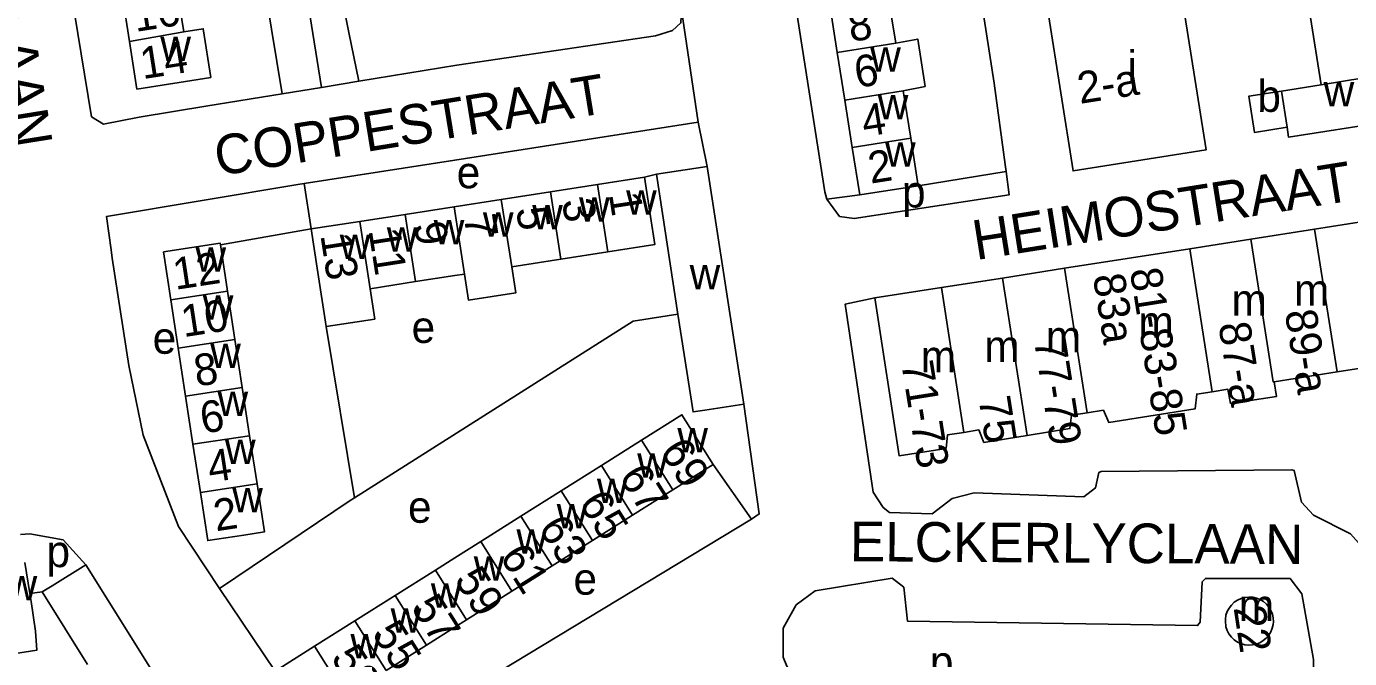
# Model space of a CAD drawing. Extents: x 159675 to 162108, y 386471 to 388472.
# Drawn here: x 160445.9 to 160612.9, y 387264.8 to 387344.6 of the extents above; entities that cross this region are included whole.
import ezdxf

# ---------------------------------------------------------------- set-up
doc = ezdxf.new("R2010")
doc.units = 0
for name, color, linetype in [('BLT_Basislijn', 7, 'Continuous'), ('BLT_Bebouwing', 7, 'Continuous'), ('BLT_Centroide', 7, 'Continuous'), ('BLT_Huisnummer', 7, 'Continuous'), ('BLT_Huisnummer_ tussenligend', 7, 'Continuous'), ('BLT_Huisnummer_reeks', 7, 'Continuous'), ('BLT_Onderverdeling_panden', 7, 'Continuous'), ('BLT_Straatnaam', 7, 'Continuous'), ('BLT_Vlakafsluiter', 7, 'Continuous')]:
    doc.layers.add(name, color=color, linetype=linetype)

msp = doc.modelspace()

# ---------------------------------------------------------------- linework, layer by layer
at = {"layer": 'BLT_Basislijn'}
for p, q in [((160463.22, 387427.52), (160478.22, 387336.11)), ((160486.63, 387343.84), (160485.9, 387347.45)), ((160487.88, 387337.71), (160486.63, 387343.84)), ((160487.88, 387337.71), (160483.16, 387336.93)), ((160478.22, 387336.11), (160483.16, 387336.93)), ((160460.17, 387333.18), (160468.84, 387334.58)), ((160525.44, 387325.97), (160523.93, 387325.58)), ((160569.58, 387326.3), (160558.48, 387324.51)), ((160481.87, 387319.06), (160480.99, 387324.78)), ((160546.94, 387322.82), (160551.1, 387323.35)), ((160470.42, 387317.06), (160481.87, 387319.06)), ((160522.52, 387307.43), (160487.33, 387285.14)), ((160522.52, 387307.43), (160528.16, 387308.3)), ((160483.78, 387306.73), (160487.33, 387285.14)), ((160537.44, 387282.44), (160532.61, 387289.34)), ((160446.36, 387273.07), (160447.91, 387273.25)), ((160477.32, 387263.27), (160470.32, 387273.7))]:
    msp.add_line(p, q, dxfattribs=at)
for points in [[(160549.16, 387459.3), (160568.08, 387337.47), (160569.46, 387327.2), (160569.58, 387326.3)], [(160526.05, 387455.64), (160546.72, 387323.73), (160546.94, 387322.82)], [(160483.16, 387336.93), (160469.1, 387424.75), (160470.61, 387425.26), (160500, 387429.61), (160515.24, 387431.98)], [(160439.29, 387423.53), (160454.15, 387333.22), (160455.66, 387332.27), (160460.17, 387333.18)], [(160528.62, 387346.73), (160528.54, 387345.06), (160527.49, 387344.1), (160525.34, 387343.42), (160500.27, 387339.73), (160487.88, 387337.71)], [(160468.84, 387334.58), (160478.22, 387336.11)], [(160530.73, 387332.53), (160500, 387327.74), (160480.99, 387324.78)], [(160531.87, 387326.96), (160530.73, 387332.53)], [(160546.94, 387322.82), (160548.56, 387320.62), (160550.41, 387320.39), (160569.96, 387323.35), (160569.58, 387326.3)], [(160480.99, 387324.78), (160480.21, 387324.66), (160456.04, 387320.63), (160456.62, 387316.43), (160456.78, 387315.39)], [(160456.78, 387315.39), (160458.88, 387301.82), (160460.68, 387293.03), (160465.15, 387281.49), (160470.32, 387273.7)], [(160553.02, 387310.36), (160549.26, 387309.56), (160552.79, 387285.85), (160554.05, 387283.92), (160554.88, 387283.26), (160560.24, 387283.11), (160562.77, 387285.05), (160565.57, 387285.77), (160579.38, 387285.26), (160580.86, 387286.37), (160581.3, 387288.33), (160581.59, 387288.44), (160605.64, 387288.67), (160605.92, 387288.58), (160606.88, 387284.56), (160608.37, 387282.92), (160613.05, 387280.6), (160617.04, 387276.06), (160618.08, 387273.69), (160619.73, 387264.46)], [(160537.44, 387282.44), (160538.43, 387283.1), (160536.5, 387296.96)], [(160487.33, 387285.14), (160486.78, 387284.77), (160470.32, 387273.7)], [(160537.44, 387282.44), (160500, 387259.82), (160488.67, 387252.68)], [(160453.42, 387276.69), (160450.57, 387279.81), (160446.36, 387280.58), (160445.19, 387280.51)], [(160608.39, 387263.31), (160608.39, 387264.71), (160606.91, 387273.02), (160605.41, 387274.93), (160594.73, 387274.96), (160594.31, 387274.52), (160594.06, 387269.42), (160593.75, 387269.01), (160557.12, 387269.57), (160556.66, 387273.85), (160555.19, 387274.98), (160545.49, 387273.39), (160543.1, 387271.61), (160541.45, 387268.66), (160541.45, 387265), (160541.92, 387263.87), (160547, 387256.8), (160547.57, 387254.03)]]:
    msp.add_lwpolyline(points, dxfattribs=at)
at = {"layer": 'BLT_Bebouwing'}
for p, q in [((160465.79, 387343.95), (160464.85, 387349.92)), ((160458, 387348.73), (160458.94, 387342.73)), ((160547.32, 387347.31), (160548.26, 387341.32)), ((160555.65, 387342.49), (160554.7, 387348.47)), ((160458.94, 387342.73), (160459.88, 387336.72)), ((160548.26, 387341.32), (160549.21, 387335.33)), ((160604.32, 387336.46), (160609.33, 387337.25)), ((160557.54, 387330.51), (160556.59, 387336.5)), ((160549.21, 387335.33), (160550.15, 387329.34)), ((160558.48, 387324.51), (160557.54, 387330.51)), ((160550.15, 387329.34), (160551.1, 387323.35)), ((160518, 387324.66), (160523.93, 387325.58)), ((160531.87, 387326.96), (160525.44, 387325.97)), ((160536.5, 387296.96), (160531.87, 387326.96)), ((160512.07, 387323.74), (160518, 387324.66)), ((160551.1, 387323.35), (160558.48, 387324.51)), ((160499.91, 387321.86), (160505.87, 387322.78)), ((160505.87, 387322.78), (160512.07, 387323.74)), ((160493.72, 387320.9), (160488, 387320.01)), ((160499.91, 387321.86), (160493.72, 387320.9)), ((160488, 387320.01), (160481.87, 387319.06)), ((160608.52, 387319.04), (160600.47, 387317.78)), ((160600.47, 387317.78), (160592.76, 387316.57)), ((160463.24, 387316.18), (160464.17, 387310.11)), ((160513.38, 387315.25), (160519.31, 387316.17)), ((160592.76, 387316.57), (160576.95, 387314.1)), ((160507.19, 387314.29), (160513.38, 387315.25)), ((160576.95, 387314.1), (160569.11, 387312.87)), ((160495.04, 387312.41), (160489.31, 387311.52)), ((160500, 387313.18), (160495.04, 387312.41)), ((160500, 387313.18), (160501.23, 387313.37)), ((160569.11, 387312.87), (160561.42, 387311.67)), ((160471.32, 387311.2), (160472.25, 387305.12)), ((160561.42, 387311.67), (160553.02, 387310.36)), ((160464.17, 387310.11), (160465.1, 387304.03)), ((160465.1, 387304.03), (160466.03, 387297.95)), ((160472.25, 387305.12), (160473.18, 387299.05)), ((160603.42, 387299.77), (160611.35, 387301.01)), ((160473.18, 387299.05), (160474.11, 387292.97)), ((160466.03, 387297.95), (160466.96, 387291.88)), ((160474.11, 387292.97), (160475.04, 387286.9)), ((160518.51, 387289.21), (160523.58, 387292.41)), ((160466.96, 387291.88), (160467.89, 387285.8)), ((160513.43, 387286.02), (160518.51, 387289.21)), ((160532.61, 387289.34), (160527.53, 387286.14)), ((160508.35, 387282.82), (160513.43, 387286.02)), ((160527.53, 387286.14), (160522.45, 387282.94)), ((160503.27, 387279.62), (160508.35, 387282.82)), ((160522.45, 387282.94), (160517.38, 387279.75)), ((160500, 387277.56), (160503.27, 387279.62)), ((160517.38, 387279.75), (160512.3, 387276.55)), ((160500, 387277.56), (160497.55, 387276.01)), ((160446.36, 387273.07), (160445.76, 387276.97)), ((160469.44, 387251.09), (160453.42, 387276.69)), ((160497.55, 387276.01), (160492.47, 387272.82)), ((160512.3, 387276.55), (160507.22, 387273.35)), ((160453.66, 387264.07), (160447.91, 387273.25)), ((160492.47, 387272.82), (160487.39, 387269.62)), ((160507.22, 387273.35), (160501.49, 387269.74)), ((160487.39, 387269.62), (160482.31, 387266.42)), ((160496.42, 387266.55), (160500, 387268.8)), ((160501.49, 387269.74), (160500, 387268.8)), ((160482.31, 387266.42), (160477.32, 387263.27)), ((160491.34, 387263.35), (160496.42, 387266.55))]:
    msp.add_line(p, q, dxfattribs=at)
for points in [[(160609.33, 387337.25), (160607.26, 387350.28), (160593.18, 387348.04)], [(160574.91, 387346.1), (160578.04, 387326.38), (160594.82, 387329.04), (160591.83, 387347.87)], [(160459.88, 387336.72), (160469.21, 387338.18), (160468.25, 387344.33), (160465.79, 387343.95)], [(160556.59, 387336.5), (160559.36, 387337.05), (160558.42, 387343.02), (160555.65, 387342.49)], [(160605.05, 387331.89), (160600.93, 387331.23), (160600.21, 387335.8), (160604.32, 387336.46)], [(160605.05, 387331.89), (160605.24, 387330.63), (160617.65, 387332.6)], [(160519.31, 387316.17), (160525.24, 387317.09), (160524.69, 387320.64), (160523.93, 387325.58)], [(160525.44, 387325.97), (160526.2, 387321.02), (160528.16, 387308.3)], [(160639.2, 387305.37), (160636.38, 387323.4), (160608.52, 387319.04)], [(160481.87, 387319.06), (160482.63, 387314.12), (160483.78, 387306.73)], [(160470.42, 387317.06), (160470.39, 387317.28), (160463.24, 387316.18)], [(160471.32, 387311.2), (160471.14, 387312.33), (160470.42, 387317.06)], [(160501.23, 387313.37), (160501.74, 387310.07), (160507.7, 387310.99), (160507.19, 387314.29)], [(160489.31, 387311.52), (160489.91, 387307.68), (160483.78, 387306.73)], [(160553.02, 387310.36), (160556.07, 387290.43), (160562, 387291.36), (160562.17, 387293.06), (160564.23, 387293.39)], [(160528.16, 387308.3), (160530.07, 387295.97), (160531.56, 387296.2), (160536.5, 387296.96)], [(160611.35, 387301.01), (160623.05, 387302.84)], [(160595.58, 387298.52), (160597.57, 387298.84), (160597.91, 387297.04), (160603.7, 387297.91), (160603.42, 387299.77)], [(160579.81, 387295.86), (160581.86, 387296.19), (160582.55, 387294.62), (160593.45, 387296.36), (160593.65, 387298.21), (160595.58, 387298.52)], [(160523.58, 387292.41), (160528.66, 387295.61), (160532.61, 387289.34)], [(160572.22, 387292.99), (160577.64, 387293.86), (160577.82, 387295.55), (160579.8, 387295.86)], [(160564.23, 387293.39), (160566.14, 387293.69), (160566.77, 387292.12), (160572.22, 387292.99)], [(160467.89, 387285.8), (160468.82, 387279.72), (160473.37, 387280.42), (160475.97, 387280.82), (160475.04, 387286.9)], [(160447.91, 387273.25), (160449.18, 387274.04), (160453.42, 387276.69)], [(160446.36, 387273.07), (160446.52, 387272.03), (160447.1, 387268.3), (160447.25, 387265.88), (160441.34, 387264.97), (160440.97, 387267.36)], [(160603.31, 387269.48), (160603.28, 387269.97), (160603.18, 387270.45), (160603, 387270.91), (160602.74, 387271.33), (160602.43, 387271.71), (160602.05, 387272.03), (160601.63, 387272.28), (160601.18, 387272.47), (160600.7, 387272.57), (160600.2, 387272.6), (160599.71, 387272.55), (160599.24, 387272.42), (160598.79, 387272.22), (160598.38, 387271.94), (160598.02, 387271.6), (160597.73, 387271.21), (160597.49, 387270.78), (160597.33, 387270.31), (160597.25, 387269.83), (160597.25, 387269.34), (160597.29, 387269.09)], [(160597.29, 387269.09), (160597.33, 387268.85), (160597.48, 387268.38), (160597.71, 387267.95), (160598.01, 387267.55), (160598.36, 387267.21), (160598.77, 387266.93), (160599.22, 387266.73), (160599.69, 387266.59), (160600.18, 387266.54), (160600.67, 387266.56), (160601.15, 387266.66), (160601.61, 387266.84), (160602.03, 387267.1), (160602.41, 387267.41), (160602.73, 387267.79), (160602.99, 387268.21), (160603.17, 387268.66), (160603.28, 387269.14), (160603.31, 387269.48)]]:
    msp.add_lwpolyline(points, dxfattribs=at)
at = {"layer": 'BLT_Onderverdeling_panden'}
for p, q in [((160458.94, 387342.73), (160465.79, 387343.95)), ((160548.26, 387341.32), (160555.65, 387342.49)), ((160609.33, 387337.25), (160614.72, 387338.14)), ((160549.21, 387335.33), (160556.59, 387336.5)), ((160604.32, 387336.46), (160605.05, 387331.89)), ((160550.15, 387329.34), (160557.54, 387330.51)), ((160518, 387324.66), (160519.31, 387316.17)), ((160505.87, 387322.78), (160507.19, 387314.29)), ((160512.07, 387323.74), (160513.38, 387315.25)), ((160493.72, 387320.9), (160495.04, 387312.41)), ((160499.91, 387321.86), (160501.23, 387313.37)), ((160488, 387320.01), (160489.31, 387311.52)), ((160611.35, 387301.01), (160608.52, 387319.04)), ((160595.58, 387298.52), (160592.76, 387316.57)), ((160579.81, 387295.86), (160576.95, 387314.1)), ((160572.22, 387292.99), (160569.11, 387312.87)), ((160464.17, 387310.11), (160471.32, 387311.2)), ((160564.23, 387293.39), (160561.42, 387311.67)), ((160465.1, 387304.03), (160472.25, 387305.12)), ((160466.03, 387297.95), (160473.18, 387299.05)), ((160466.96, 387291.88), (160474.11, 387292.97)), ((160527.53, 387286.14), (160523.58, 387292.41)), ((160522.45, 387282.94), (160518.51, 387289.21)), ((160467.89, 387285.8), (160475.04, 387286.9)), ((160517.38, 387279.75), (160513.43, 387286.02)), ((160512.3, 387276.55), (160508.35, 387282.82)), ((160507.22, 387273.35), (160503.27, 387279.62)), ((160501.49, 387269.74), (160497.55, 387276.01)), ((160496.42, 387266.55), (160492.47, 387272.82)), ((160491.34, 387263.35), (160487.39, 387269.62)), ((160486.26, 387260.15), (160482.31, 387266.42))]:
    msp.add_line(p, q, dxfattribs=at)
msp.add_lwpolyline([(160603.42, 387299.77), (160603.29, 387299.75), (160600.47, 387317.78)], dxfattribs=at)
at = {"layer": 'BLT_Vlakafsluiter'}
msp.add_line((160528.62, 387346.73), (160530.73, 387332.53), dxfattribs=at)

# ---------------------------------------------------------------- texts
at = {"layer": 'BLT_Centroide'}
for s, p in [('w', (160462.84, 387340.25)), ('w', (160552.43, 387338.91)), ('i', (160584.88, 387337.58)), ('b', (160601.29, 387333.84)), ('w', (160609.65, 387334.53)), ('w', (160553.38, 387332.91)), ('w', (160554.31, 387326.94)), ('e', (160500.24, 387324.2)), ('w', (160521.62, 387320.88)), ('p', (160556.44, 387321.77)), ('w', (160515.69, 387319.97)), ('w', (160503.55, 387318.08)), ('w', (160509.77, 387319.03)), ('w', (160491.42, 387316.19)), ('w', (160497.34, 387317.12)), ('w', (160485.48, 387315.28)), ('w', (160467.28, 387313.69)), ('w', (160529.64, 387311.45)), ('m', (160605.91, 387309.36)), ('w', (160468.2, 387307.62)), ('m', (160598.03, 387308.11)), ('e', (160494.55, 387304.68)), ('m', (160586.28, 387305.33)), ('e', (160461.87, 387303.31)), ('m', (160574.59, 387303.47)), ('w', (160469.14, 387301.53)), ('m', (160558.81, 387300.98)), ('m', (160566.83, 387302.27)), ('w', (160470.06, 387295.47)), ('w', (160528.09, 387290.88)), ('w', (160471, 387289.38)), ('w', (160523.02, 387287.69)), ('w', (160517.94, 387284.47)), ('w', (160471.92, 387283.31)), ('e', (160494.1, 387281.98)), ('w', (160512.86, 387281.28)), ('w', (160507.78, 387278.09)), ('p', (160448.47, 387276.38)), ('w', (160502.39, 387274.69)), ('e', (160514.98, 387272.9)), ('w', (160443.44, 387272.19)), ('w', (160496.98, 387271.28)), ('m', (160598.95, 387269.56)), ('w', (160491.91, 387268.09)), ('w', (160486.83, 387264.88)), ('p', (160559.96, 387262.43))]:
    msp.add_text(s, height=4, dxfattribs=at).set_placement(p)
at = {"layer": 'BLT_Huisnummer'}
for s, rotation, p in [('14', 8.9023, (160460.62, 387337.96)), ('6', 8.9647, (160550.76, 387336.85)), ('2', 8.9647, (160552.48, 387324.77)), ('1', 278.8197, (160519.44, 387323.45)), ('5', 278.8197, (160507.72, 387321.61)), ('9', 278.8197, (160494.84, 387319.71)), ('13', 278.8197, (160483.03, 387318.27)), ('12', 8.6959, (160464.74, 387311.37)), ('6', 8.6959, (160468.18, 387293.22)), ('75', 279.0257, (160566.09, 387297.66)), ('69', 302.203, (160525.81, 387291.03)), ('2', 8.6959, (160469.86, 387280.89)), ('63', 302.203, (160510.46, 387281.32)), ('59', 302.203, (160499.85, 387274.81)), ('22', 278.6115, (160598.28, 387271.26)), ('55', 302.203, (160489.45, 387268))]:
    msp.add_text(s, height=4, rotation=rotation, dxfattribs=at).set_placement(p)
at = {"layer": 'BLT_Huisnummer_ tussenligend'}
for s, rotation, p in [('16', 8.9164, (160459.71, 387343.92)), ('8', 8.965, (160549.96, 387342.65)), ('4', 8.965, (160551.68, 387330.67)), ('3', 278.8187, (160513.52, 387322.64)), ('7', 278.8187, (160501.12, 387320.63)), ('11', 278.8187, (160489.1, 387318.9)), ('10', 8.6997, (160465.78, 387305.4)), ('8', 8.6997, (160467.4, 387299.16)), ('4', 8.6997, (160469.12, 387287.04)), ('67', 302.203, (160520.62, 387287.78)), ('65', 302.203, (160515.58, 387284.45)), ('61', 302.203, (160505.58, 387277.72)), ('57', 302.203, (160494.38, 387271.33)), ('53', 302.203, (160484.29, 387264.96))]:
    msp.add_text(s, height=4, rotation=rotation, dxfattribs=at).set_placement(p)
at = {"layer": 'BLT_Huisnummer_reeks'}
for s, rotation, p in [('2-a', 9.0243, (160578.9, 387334.84)), ('81-83-85', 279.0267, (160585.18, 387313.88)), ('83a', 279.0267, (160580.52, 387313.15)), ('89-a', 279.0258, (160604.74, 387308.62)), ('87-a', 279.0253, (160596.36, 387307.04)), ('77-79', 279.0257, (160573.08, 387305.02)), ('71-73', 279.0257, (160556.34, 387302.14))]:
    msp.add_text(s, height=4, rotation=rotation, dxfattribs=at).set_placement(p)
at = {"layer": 'BLT_Straatnaam'}
for s, height, rotation, p in [('CUWAERTLAAN', 4.9999, 279.1093, (160436.23, 387379.69)), ('COPPESTRAAT', 5, 9.2467, (160470.11, 387325.73)), ('HEIMOSTRAAT', 5, 9.0105, (160565.78, 387315.12)), ('ELCKERLYCLAAN', 5, 359.6217, (160549.85, 387277.13))]:
    msp.add_text(s, height=height, rotation=rotation, dxfattribs=at).set_placement(p)

doc.saveas('drawing.dxf')
